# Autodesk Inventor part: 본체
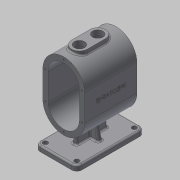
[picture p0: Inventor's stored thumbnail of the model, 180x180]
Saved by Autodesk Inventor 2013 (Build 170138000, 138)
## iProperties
Created: 2016-12
Part Number: 본체
Material: 일반
Document SubType Name: Modeling
Designer: mduedu
Density: 1 g/cm^3
Mass: 432.112 g
Surface Area: 1014.94 cm^2
Volume: 432.112 cm^3
Author: mduedu
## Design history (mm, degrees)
sketch "스케치1"
  geometry: L1 (40, -25)-(40, 25); L2 (-40, 25)-(-40, -25); L3 (-40, -25)-(40, 25); L4 (40, -25)-(-40, 25); L5 (0, 25)-(0, -25); A1 r 40 centre (0, 25) between (40, 25) and (-40, 25); A2 r 40 centre (0, -25) between (-40, -25) and (40, -25); 1 further point
  constraints: 10 end point, 4 point on circle, 3 tangent, 2 centre point, 2 midpoint, 2 parallel, 1 vertical
  dimensions: "d0" = 130 dimension on A2 A1; "d2" = 80 distance between parallel lines of L1 L2
extrude "돌출1" new body sketch "스케치1" stored distance "d3" = 100; taper "d4" = 0 deg
feature "쉘1" dims "d5" = 10
sketch "스케치2"
  geometry: L1 (-90, 65)-(-100, 65); L2 (-100, 65)-(-100, -65); L3 (-100, -65)-(-90, -65); L4 (-90, -65)-(-90, 65); 2 further points
  constraints: 8 end point, 2 parallel, 1 horizontal, 1 horizontal alignment, 1 midpoint, 1 perpendicular
  dimensions: "d6" = 100 distance from line of L2 point (0, 0); "d7" = 130 distance of L1.end L2.end; "d8" = 10 distance of L2.end L3.end
extrude "돌출2" join sketch "스케치2" stored distance "d9" = 80; taper "d10" = 0 deg
fillet "모깎기1" dims "d11" = 10
sketch "스케치3"
  geometry: L1 (-10, 10)-(-10, 120) reference; L2 (60, 0)-(0, 0) reference; L3 (70, 120)-(70, 10) reference; L4 (0, 130)-(60, 130) reference; A1 r 10 centre (0, 120) between (0, 130) and (-10, 120) reference; A2 r 10 centre (0, 10) between (-10, 10) and (0, 0) reference; A3 r 10 centre (60, 10) between (60, 0) and (70, 10) reference; A4 r 10 centre (60, 120) between (70, 120) and (60, 130) reference; 5 further points
  constraints: 4 coincident
hole "구멍1" sketch "스케치3" at (60, 120), (60, 10), (0, 10), (0, 120) diameter "d12" = 9; stored, may be unused: countersink angle "d16" = 90 deg, drill point angle "d18" = 118 deg; dims "d13" = 6, "d14" = 4, "d15" = 2, "d17" = 8
sketch "스케치5"
  geometry: L1 (34, 35)-(26, 35); L2 (26, 35)-(26, 95); L3 (26, 95)-(34, 95); L4 (34, 95)-(34, 35); L5 (34, 35)-(26, 95); L6 (26, 35)-(34, 95); 1 further point
  constraints: 12 end point, 2 midpoint, 2 parallel, 1 horizontal, 1 perpendicular
  dimensions: "d22" = 8 distance of L2.end L3.end; "d24" = 60 distance of L1.end L2.end
extrude "돌출3" join sketch "스케치5" stored distance "d25" = 80; taper "d26" = 0 deg
feature "면 기울기1" dims angle "d27" = 5 deg
sketch "스케치6"
  geometry: L1 (-30, -90)-(30, -90) reference; L2 (-15.072, -62.052)-(-20, -90); A1 r 40 centre (0, -25) between (-40, -25) and (40, -25) reference; 1 further point
  constraints: 2 end point, 1 point on circle, 1 point on line
  dimensions: "d28" = 20 horizontal distance of A1.centre L2.end; "d29" = 80 deg angle of L2 L1
feature "리브1" sketch "스케치6" dims "d30" = 1, "d31" = 8, "d32" = 0, "d33" = 0, "d34" = 1, "d35" = 1
fillet "모깎기2" dims "d36" = 3
fillet "모깎기3" dims "d37" = 3, "d38" = 3
node "작업 평면1"
sketch "스케치9"
  geometry: 1 further point
sketch "스케치7"
  geometry: L1 (40, 50)-(-40, 50) reference; C1 r 15 at (0, 20); 1 further point
  constraints: 1 centre point, 1 vertical alignment
  dimensions: "d40" = 30 diameter of C1; "d41" = 30 distance from line of C1.centre L1
extrude "돌출4" join sketch "스케치7" stored distance "d42" = 80; taper "d43" = 0 deg
sketch "스케치15"
  geometry: C1 r 15 at (0, -15); C2 r 15 at (0, 20) reference; 1 further point
  constraints: 1 centre point, 1 vertical alignment
  dimensions: "d83" = 30 diameter of C1; "d84" = 35 distance of C1.centre C2.centre
extrude "돌출6" join sketch "스케치15" stored distance "d85" = 10; taper "d86" = 0 deg
hole "구멍2" diameter "d46" = 20; stored, may be unused: countersink angle "d50" = 90 deg, drill point angle "d52" = 118 deg; dims "d44" = 10, "d45" = 10, "d47" = 6, "d48" = 4, "d49" = 2, "d51" = 8
hole "구멍6" diameter "d89" = 20; stored, may be unused: countersink angle "d93" = 90 deg, drill point angle "d95" = 118 deg; dims "d87" = 10, "d88" = 10, "d90" = 6, "d91" = 4, "d92" = 2, "d94" = 8
node "작업 평면2"
sketch "스케치8"
  geometry: C1 r 15 at (0, 0) reference; C2 r 15 at (0, 0); 1 further point
  constraints: 1 centre point, 1 coincident
  dimensions: "d55" = 30 diameter of C2
extrude "돌출5" cut sketch "스케치8" stored distance "d56" = 80; taper "d57" = 0 deg
sketch "스케치16"
  geometry: C1 r 15 at (0, 35); 2 further points
  constraints: 1 centre point, 1 coincident, 1 vertical alignment
  dimensions: "d96" = 30 diameter of C1
extrude "돌출7" cut sketch "스케치16" stored distance "d97" = 10; taper "d98" = 0 deg
sketch "스케치17"
  geometry: L1 (15, 0)-(15, -35); L2 (-15, 0)-(-15, -35); C1 r 10 at (0, 0) reference; C2 r 10 at (0, -35) reference; A1 r 15 centre (0, 0) between (15, 0) and (-15, 0) reference; A2 r 15 centre (0, -35) between (15, -35) and (-15, -35) reference; 1 further point
  constraints: 4 end point, 4 point on circle, 3 tangent, 1 vertical
extrude "돌출8" join sketch "스케치17" stored distance "d99" = 10; taper "d100" = 0 deg
fillet "모깎기5" dims "d101" = 3
chamfer "모따기1" distance "d58" = 1; stored, may be unused: second distance "d59" = 2, angle "d60" = 45 deg
sketch "스케치10"
  geometry: 2 further points
  constraints: 1 coincident, 1 other
feature "엠보싱1" sketch "스케치10" dims "d0" = 130, "d2" = 80, "d11" = 10, "d61" = 0.5, "d62" = 0
sketch "스케치11"
  geometry: 1 further point
hole "구멍3" sketch "스케치11" at (0, 60) diameter "d63" = 3.242; stored, may be unused: countersink angle "d67" = 90 deg, drill point angle "d69" = 120 deg; dims "d64" = 8.6, "d65" = 4, "d66" = 2, "d68" = 10.6
sketch "스케치12"
  geometry: 1 further point
hole "구멍5" sketch "스케치12" at (0, 60) diameter "d70" = 3.242; stored, may be unused: countersink angle "d74" = 90 deg, drill point angle "d76" = 120 deg; dims "d71" = 8.6, "d72" = 4, "d73" = 2, "d75" = 10.6
node "솔리드1"
mirror "대칭1"
pattern_linear "직사각형 패턴1"
pattern_linear "직사각형 패턴2"
node "투영된 루프1"
sketch "스케치13"
  geometry: L1 (-40, 25)-(-40, -25) reference; L2 (40, -25)-(40, 25) reference; L3 (35, 25)-(35, -25); L4 (-35, -25)-(-35, 25); A1 r 40 centre (0, 25) between (40, 25) and (-40, 25) reference; A2 r 40 centre (0, -25) between (-40, -25) and (40, -25) reference; A3 r 35 centre (0, 25) between (35, 25) and (-35, 25); A4 r 35 centre (0, -25) between (-35, -25) and (35, -25); 2 further points
  constraints: 5 point on circle, 4 end point, 2 centre point, 3 other
  dimensions: "d77" = 5 distance between parallel lines of L3 L2
sketch "스케치14"
  geometry: L1 (-40, 25)-(-40, -25) reference; L2 (40, -25)-(40, 25) reference; L3 (35, 25)-(35, -25); L4 (-35, -25)-(-35, 25); A1 r 40 centre (0, 25) between (40, 25) and (-40, 25) reference; A2 r 40 centre (0, -25) between (-40, -25) and (40, -25) reference; A3 r 35 centre (0, 25) between (35, 25) and (-35, 25); A4 r 35 centre (0, -25) between (-35, -25) and (35, -25); 2 further points
  constraints: 5 point on circle, 4 end point, 2 centre point, 3 other
  dimensions: "d80" = 5 distance between parallel lines of L2 L3
node "투영된 루프3"
node "투영된 루프4"
node "투영된 루프5"
